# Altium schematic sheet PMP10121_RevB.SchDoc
size 431 x 279 mm; Date: Not shown in title block; ApprovedBy: Not shown in title block; CheckedBy: Not shown in title block; Author: Not shown in title block; CompanyName: Not shown in title block; Engineer: Not shown in title block; Organization: Not shown in title block; Address1: Not shown in title block; Address2: Not shown in title block; Address3: Not shown in title block; Address4: Not shown in title block; DocumentNumber: 1; Revision: Use project parameter SCH_Rev; SheetNumber: 2; SheetTotal: 3; PageSetup: Record=PageOptions¦CenterHorizontal=True¦CenterVertical=True¦PrintScale=1.00¦XCorrection=1.00¦YCorrection=1.00¦PrintKind=0¦BorderSize=5000000¦LeftOffset=0¦BottomOffset=0¦Orientation=2¦PaperLength=1000¦PaperWidth=1000¦Scale=100¦PaperSource=15¦PrintQuality=600¦MediaType=1¦DitherType=10¦PaperKind=Letter¦PrintScaleMode=1
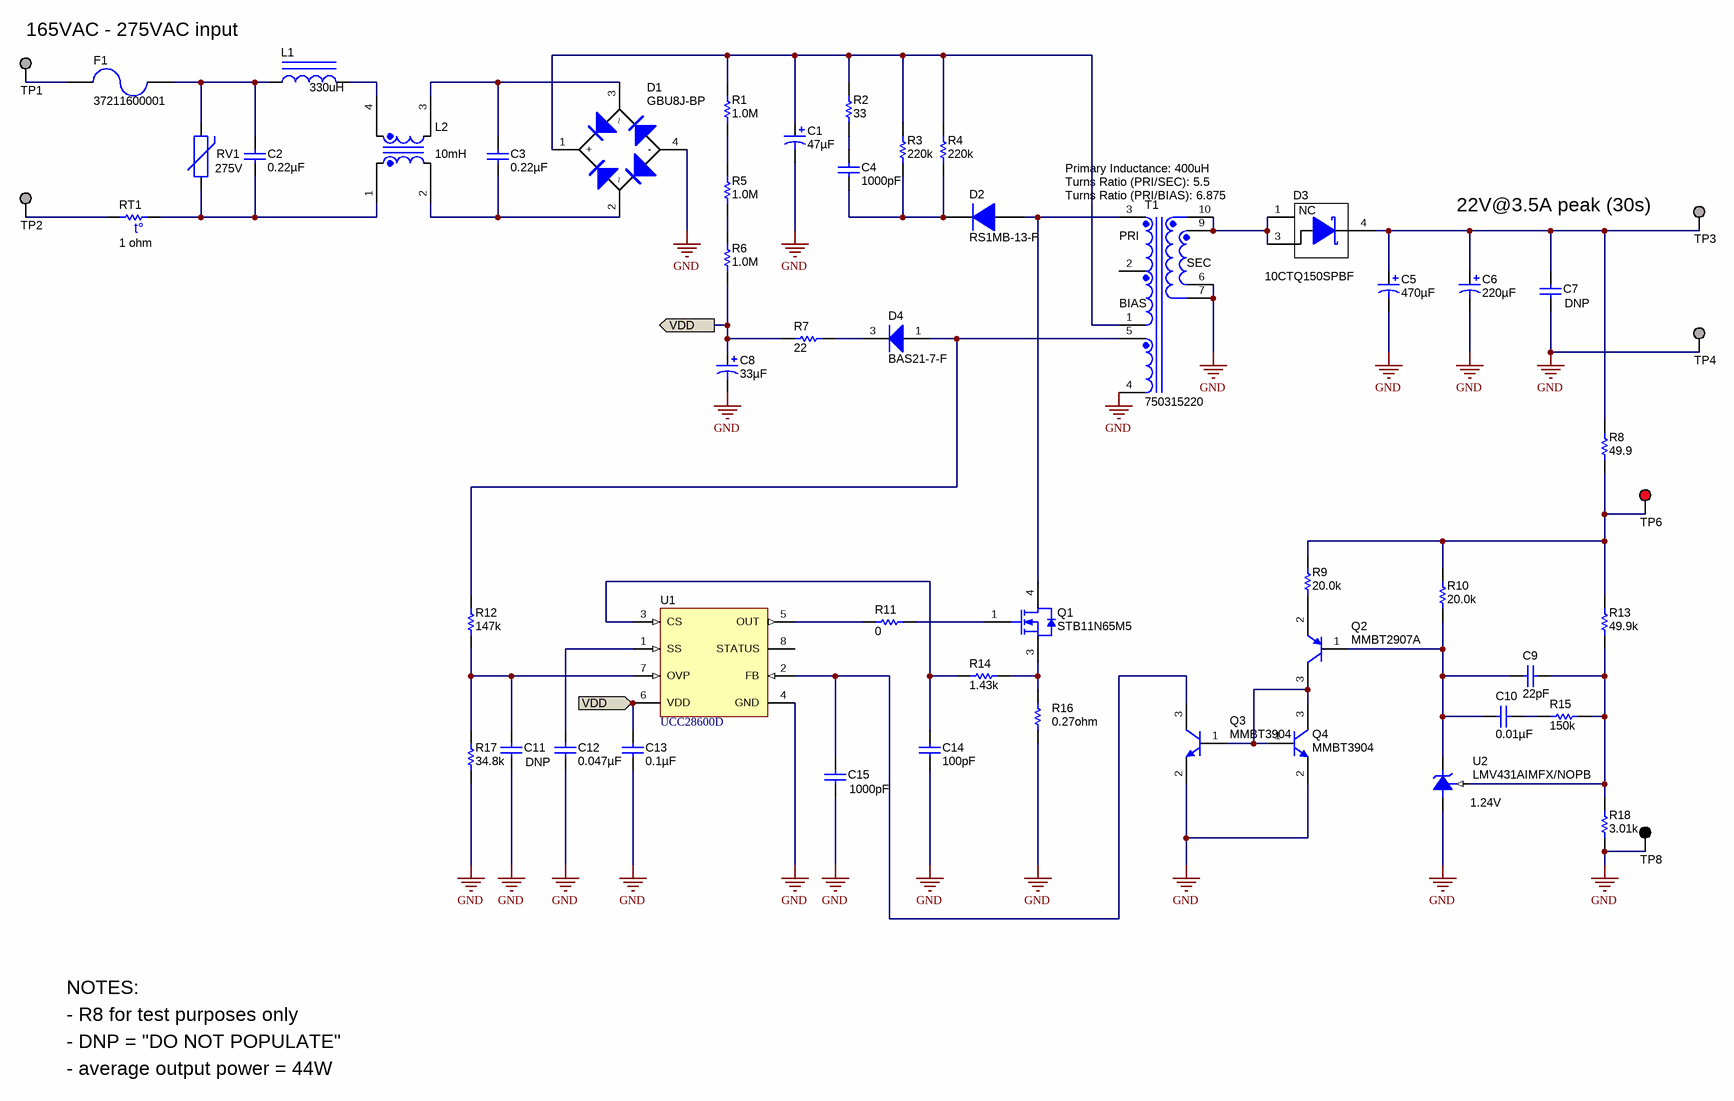
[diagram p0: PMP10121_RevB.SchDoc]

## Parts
C1  ValueDisplayed: 47µF  [CAPPR7.5-18X31.5]  (hidden comment: EEUED2W470)
C2  ValueDisplayed: 0.22µF  [B32922_12.5mm]  (hidden comment: B32922C3224K)
C3  ValueDisplayed: 0.22µF  [B32922_12.5mm]  (hidden comment: B32922C3224K)
C4  ValueDisplayed: 1000pF  [1206]  (hidden comment: GRM31B5C2J102JW01L)
C5  ValueDisplayed: 470µF  [KZN_1000x2000]  (hidden comment: EKZN350ELL471MJ20S)
C6  ValueDisplayed: 220µF  [KZN_800x1500]  (hidden comment: EKZN350ELL221MH15D)
C7  value DNP  [1210]  (hidden comment: Used in BOM report)
C8  ValueDisplayed: 33µF  [SM_RADIAL_E]  (hidden comment: EEE-FC1V330P)
C9  ValueDisplayed: 22pF  [0603]  (hidden comment: GRM1885C1H220JA01D)
C10  ValueDisplayed: 0.01µF  [0805_HV]  (hidden comment: GRM216R71H103KA01D)
C11  value DNP  [0603]  (hidden comment: C0603C100J5GACTU)
C12  ValueDisplayed: 0.047µF  [0603]  (hidden comment: C1608X7R1H473K)
C13  ValueDisplayed: 0.1µF  [0805_HV]  (hidden comment: GRM21BR71H104KA01L)
C14  ValueDisplayed: 100pF  [0603]  (hidden comment: C0603C101J5GAC)
C15  value 1000pF  [0603]  (hidden comment: C1608C0G1H102J)
D1  GBU8J-BP  [GBU]
D2  RS1MB-13-F  [SMB]
D3  10CTQ150SPBF  [DDPAK]
D4  BAS21-7-F  [SOT-23]
F1  37211600001  [FUSE_372]
L1  value 330uH  [IND_MSS1210]  (hidden comment: MSS1210-334KE)
L2  ValueDisplayed: 10mH  [IND_WE-CMB_M]  (hidden comment: 744823210)
Q1  STB11N65M5  [DDPAK]
Q2  MMBT2907A  [SOT-23]
Q3  MMBT3904  [SOT-23]
Q4  MMBT3904  [SOT-23]
R1  ValueDisplayed: 1.0M  [0805_HV]  (hidden comment: CRCW08051M00JNEA)
R2  ValueDisplayed: 33  [2010]  (hidden comment: CRCW201033R0JNEF)
R3  ValueDisplayed: 220k  [2010]  (hidden comment: CRCW2010220KFKEF)
R4  ValueDisplayed: 220k  [2010]  (hidden comment: CRCW2010220KFKEF)
R5  ValueDisplayed: 1.0M  [0805_HV]  (hidden comment: CRCW08051M00JNEA)
R6  ValueDisplayed: 1.0M  [0805_HV]  (hidden comment: CRCW08051M00JNEA)
R7  ValueDisplayed: 22  [0805_HV]  (hidden comment: CRCW080522R0JNEA)
R8  ValueDisplayed: 49.9  [0603]  (hidden comment: CRCW060349R9FKEA)
R9  ValueDisplayed: 20.0k  [0603]  (hidden comment: CRCW060320K0FKEA)
R10  ValueDisplayed: 20.0k  [0603]  (hidden comment: CRCW060320K0FKEA)
R11  ValueDisplayed: 0  [0805_HV]  (hidden comment: CRCW08050000Z0EA)
R12  ValueDisplayed: 147k  [0603]  (hidden comment: CRCW0603147KFKEA)
R13  ValueDisplayed: 49.9k  [0603]  (hidden comment: CRCW060349K9FKEA)
R14  ValueDisplayed: 1.43k  [0603]  (hidden comment: CRCW06031K43FKEA)
R15  ValueDisplayed: 150k  [0603]  (hidden comment: CRCW0603150KFKEA)
R16  value 0.27ohm  [1210]  (hidden comment: Used in BOM report)
R17  ValueDisplayed: 34.8k  [0603]  (hidden comment: CRCW060334K8FKEA)
R18  ValueDisplayed: 3.01k  [0603]  (hidden comment: CRCW06033K01FKEA)
RT1  value 1 ohm  [S237]  (hidden comment: B57237S109M)
RV1  value 275V  [VAR_S10K275E2]  (hidden comment: S10K275E2)
T1  750315220  [WURTH_750315220]
TP1  Suggest using a net name here  [Keystone1503-2]  (value not drawn)
TP2  Suggest using a net name here  [Keystone1503-2]  (value not drawn)
TP3  Suggest using a net name here  [Keystone1503-2]  (value not drawn)
TP4  Suggest using a net name here  [Keystone1503-2]  (value not drawn)
TP6  5000  [Keystone5000]  (value not drawn)
TP8  5001  [Keystone5001]  (value not drawn)
U1  UCC28600D  [D0008A_N]
U2  LMV431AIMFX/NOPB  [MF03A_N]

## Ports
VDD (in), VDD (out)

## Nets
GND: C1.2(-) C5.2(-) C6.2(-) C7.2 C8.2(-) C11.2 C12.2 C13.2 C14.2 C15.2 D1.4(-) Q3.2(E) Q4.2(E) R16.1 R17.1 R18.1 T1.4 T1.6 T1.7 TP4.1 TP8.1 U1.4(GND) U2.3(A)
VDD: C8.1(+) C13.1 R6.1 R7.1 U1.6(VDD) ; port VDD
NetC1_1: C1.1(+) D1.1(+) R1.2 R2.2 R3.2 R4.2 T1.1
NetC2_1: C2.1 F1.1 L1.1 RV1.2
NetC2_2: C2.2 L2.1 RT1.2 RV1.1
NetC3_1: C3.1 D1.3 L2.3
NetC3_2: C3.2 D1.2 L2.2
NetC4_1: C4.1 R2.1
NetC4_2: C4.2 D2.1(K) R3.1 R4.1
NetC5_1: C5.1(+) C6.1(+) C7.1 D3.4(K) R8.2 TP3.1
NetC9_1: C9.1 R13.1 R15.1 R18.2 U2.1(REF)
NetC9_2: C9.2 C10.1 Q2.1(B) R10.1 U2.2(K)
NetC10_2: C10.2 R15.2
NetC11_1: C11.1 R12.1 R17.2 U1.7(OVP)
NetC12_1: C12.1 U1.1(SS)
NetC14_1: C14.1 R14.1 U1.3(CS)
NetC15_1: C15.1 Q3.3(C) U1.2(FB)
NetD2_2: D2.2(A) Q1.4(D) T1.3
NetD3_1: D3.1(NC) D3.3(A) T1.9 T1.10
NetD4_1: D4.1(A) R12.2 T1.5
NetD4_3: D4.3(K) R7.2
NetF1_2: F1.2 TP1.1
NetL1_2: L1.2 L2.4
NetQ1_1: Q1.1(G) R11.2
NetQ1_3: Q1.3(S) R14.2 R16.2
NetQ2_2: Q2.2(E) R9.1
NetQ2_3: Q2.3(C) Q3.1(B) Q4.1(B) Q4.3(C)
NetR1_1: R1.1 R5.2
NetR5_1: R5.1 R6.2
NetR8_1: R8.1 R9.2 R10.2 R13.2 TP6.1
NetR11_1: R11.1 U1.5(OUT)
NetRT1_1: RT1.1 TP2.1

Not connected (* = marked no-connect by the designer): T1 2; U1 8(STATUS)

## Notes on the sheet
- 165VAC - 275VAC input
- (near T1) Primary Inductance: 400uH
- (near T1) Turns Ratio (PRI/SEC): 5.5
- (near T1) Turns Ratio (PRI/BIAS): 6.875
- (near T1) PRI
- 22V@3.5A peak (30s)
- (near T1) BIAS
- (near T1) SEC
- (near U2) 1.24V
- NOTES:
- - R8 for test purposes only
- - DNP = "DO NOT POPULATE"
- - average output power = 44W

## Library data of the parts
C1 = EEUED2W470: CAP, AL, 47 µF, 450 V, +/- 20%, 0.609529 ohm, TH; Manufacturer: Panasonic; Polarized: Y; CompType: Capacitor; Value: 47uF; U/M: EA; Cap_F: 0.000047; Tolerance_%: 20; VDC_V: 450; Value2: 450V; IRMS_A: 1; TaMin_C: -25; TaMax_C: 105; AC_Derating: 0.3
C2 C3 = B32922C3224K: CAP, Film, 0.22 µF, 630 V, +/- 10%, TH; Manufacturer: EPCOS Inc; Polarized: N; CompType: Capacitor; Value: 0.22uF; U/M: EA; Cap_F: 0.00000022; Tolerance_%: 10; Value1: Unknown; VDC_V: 630; Value2: 630V; TaMax_C: 110
C4 = GRM31B5C2J102JW01L: CAP, CERM, 1000 pF, 630 V, +/- 5%, C0G/NP0, 1206; Manufacturer: MuRata; Polarized: N; CompType: Capacitor; Value: 1000pF; U/M: EA; Cap_F: 0.000000001; Tolerance_%: 5; Value1: Unknown; VDC_V: 630; Value2: 630V; TaMin_C: -55; TaMax_C: 125
C5 = EKZN350ELL471MJ20S: CAP, AL, 470 µF, 35 V, +/- 20%, 0.028 ohm, TH; Manufacturer: Chemi-Con; Polarized: Y; CompType: Capacitor; Value: 470uF; U/M: EA; Cap_F: 0.00047; Tolerance_%: 20; VDC_V: 35; Value2: 35V; ESR_ohm: 0.028; IRMS_A: 2.5; TaMin_C: -40; TaMax_C: 105; Cap_Case: 10x20mm
C6 = EKZN350ELL221MH15D: CAP, AL, 220 µF, 35 V, +/- 20%, 0.059 ohm, TH; Manufacturer: Chemi-Con; Polarized: Y; CompType: Capacitor; Value: 220uF; U/M: EA; Cap_F: 0.00022; Tolerance_%: 20; VDC_V: 35; Value2: 35V; ESR_ohm: 0.059; IRMS_A: 1.6; TaMin_C: -40; TaMax_C: 105; Cap_Case: 8x15mm
C7 = Capacitor: CAP, CERM, xxxF, xxV, [TempCo], xx%, [PackageReference]; Polarized: N; U/M: EA
C8 = EEE-FC1V330P: CAP, AL, 33 µF, 35 V, +/- 20%, 0.4 ohm, SMD; Manufacturer: Panasonic; Polarized: Y; CompType: Capacitor; Value: 33uF; U/M: EA; Cap_F: 0.000033; Tolerance_%: 20; Value1: 0.4 ohm; VDC_V: 35; Value2: 35V; ESR_ohm: 0.4; IRMS_A: 0.15; TaMin_C: -40; TaMax_C: 105; Cap_Case: E
C9 = GRM1885C1H220JA01D: CAP, CERM, 22 pF, 50 V, +/- 5%, C0G/NP0, 0603; Manufacturer: MuRata; Polarized: N; CompType: Capacitor; Value: 22pF; U/M: EA; Cap_F: 0.000000000022; Tolerance_%: 5; Value1: Unknown; VDC_V: 50; Value2: 50V; TaMin_C: -55; TaMax_C: 125
C10 = GRM216R71H103KA01D: CAP, CERM, 0.01 µF, 50 V, +/- 10%, X7R, 0805; Manufacturer: MuRata; Polarized: N; CompType: Capacitor; Value: 0.01uF; U/M: EA; Cap_F: 0.00000001; Tolerance_%: 10; Value1: Unknown; VDC_V: 50; Value2: 50V; TaMin_C: -55; TaMax_C: 125; Cap_Case: 0805
C11 = C0603C100J5GACTU: CAP, CERM, 10 pF, 50 V, +/- 5%, C0G/NP0, 0603; Manufacturer: Kemet; Polarized: N; CompType: Capacitor; U/M: EA; Cap_F: 0.00000000001; Tolerance_%: 5; Value1: Unknown; VDC_V: 50; Value2: 50V; TaMin_C: -55; TaMax_C: 125
C12 = C1608X7R1H473K: CAP, CERM, 0.047 µF, 50 V, +/- 10%, X7R, 0603; Manufacturer: TDK; Polarized: N; CompType: Capacitor; Value: 0.047uF; U/M: EA; Cap_F: 0.000000047; Tolerance_%: 10; ESR_ohm: 0.0234; Value1: 0.0234 ohm; VDC_V: 50; Value2: 50V; TaMin_C: -55; TaMax_C: 125
C13 = GRM21BR71H104KA01L: CAP, CERM, 0.1 µF, 50 V, +/- 10%, X7R, 0805; Manufacturer: MuRata; Polarized: N; CompType: Capacitor; Value: 0.1uF; U/M: EA; Cap_F: 0.0000001; Tolerance_%: 10; Value1: Unknown; VDC_V: 50; Value2: 50V; TaMin_C: -55; TaMax_C: 125; Cap_Case: 0805
C14 = C0603C101J5GAC: CAP, CERM, 100 pF, 50 V, +/- 5%, C0G/NP0, 0603; Manufacturer: Kemet; Polarized: N; CompType: Capacitor; Value: 100pF; U/M: EA; Cap_F: 0.0000000001; Tolerance_%: 5; Value1: Unknown; VDC_V: 50; Value2: 50V; TaMin_C: -55; TaMax_C: 125
C15 = C1608C0G1H102J: CAP, CERM, 1000 pF, 50 V, +/- 5%, C0G/NP0, 0603; Manufacturer: TDK; Polarized: N; CompType: Capacitor; U/M: EA; Cap_F: 0.000000001; Tolerance_%: 5; ESR_ohm: 0.0563; Value1: 0.0563 ohm; VDC_V: 50; Value2: 50V; TaMin_C: -55; TaMax_C: 125
D1 = GBU8J-BP: Diode, Switching-Bridge, 420 V, 8 A, TH; Manufacturer: Micro Commercial Components; U/M: EA; Vf_V: 1; Value: 420V; Value1: 8A; Value2: 1V; Io_A: 8; Vr_V: 420; TJmax_C: 175
D2 = RS1MB-13-F: Diode, P-N, 1000 V, 1 A, SMB; Manufacturer: Diodes Inc.; U/M: EA; Vf_V: 1.3; Value: 1000V; Value1: 1A; Value2: 1.3V; Io_A: 1; Vr_V: 1000; TJmax_C: 150; RJC_CperW: 20
D3 = Diode_Schottky_A3C4: Diode, Schottky, xxV, xxA, [PackageReference]; Manufacturer: Used in BOM report; U/M: EA; Diode Configuration: 1 Pair Common Cathode; Vr_V: 150V; Current - Average Rectified (Io) (per Diode): 5A; Current - Reverse Leakage @ Vr: 50µA @ 150V
D4 = BAS21-7-F: Diode, Switching, 200 V, 0.2 A, SOT-23; Manufacturer: Diodes Inc.; U/M: EA; Vf_V: 1.25; Value: 200V; Value1: 0.2A; Value2: 1.25V; Io_A: 0.2; Vr_V: 200; TJmax_C: 150; RJC_CperW: 500
F1 = 37211600001: Fuse, 1.6 A, 250 V, TH; Manufacturer: Littelfuse; U/M: EA; OpeningTime_200%_max: 2; VDC_V: 250; Irating_A: 1.6; Vdrop: 0.095; Soldering_Wave_MaxTemp_C: 260; Soldering_Wave_MaxTime_s: 5
L1 = MSS1210-334KE: Inductor, Shielded, Ferrite, 330 µH, 1.7 A, 0.317 ohm, SMD; Manufacturer: Coilcraft; Ind_H: 330.0E-6; ValueDisplayed: 330µH; Imax_A: 1.7; Irms: 1.7A @ 40C rise; Isat: 2.2A @ 30% inductance drop; DCR_ohm: 0.317; Value2: 1.7A
L2 = 744823210: Coupled inductor, 10 mH, 2 A, 0.125 ohm, +/- 30%, TH; Manufacturer: Wurth Elektronik eiSos; SymbolCreator: a0412235; Ind_H: 10.0E-3; DCR_ohm: 0.125; Isat: 2; Tolerance_%: 30; Value: 10mH
Q1 = STB11N65M5: MOSFET, N-CH, 710 V, 9 A, DDPAK; Manufacturer: STMicroelectronics; Alternate Manufacturer: None; U/M: EA; ChType: N; Value: 710V; VdsMax_V: 710; Value1: ? ohm; Value2: 17 nC; QgTyp_nC: 17; Vgs_V: 25; IdsMax_A: 9
Q2 = MMBT2907A, Fairchild Semiconductor: Transistor, PNP, 60 V, 0.8 A, SOT-23; CompType: BJT; PNP: 1; NPN: 0; Vceo_V: 60; Vcesat1_V: 1.6; Value: 60 V; IcRated_A: 0.8; Value1: 0.8 A; HfeMax: 300; TaMin_C: -55; TaMax_C: 150; U/M: EA
Q3 Q4 = MMBT3904, Fairchild Semiconductor: Transistor, NPN, 40 V, 0.2 A, SOT-23; CompType: BJT; PNP: 0; NPN: 1; Vceo_V: 40; Vcesat1_V: 0.2; Value: 40 V; Value1: 0.2 A; HfeMax: 300; TaMin_C: -55; TaMax_C: 150; U/M: EA
R1 R5 R6 = CRCW08051M00JNEA: RES, 1.0 M, 5%, 0.125 W, 0805; Manufacturer: Vishay-Dale; CompType: Resistor; Value: 1.0Meg; Res_ohm: 1000000; Value_Code: 1M00; Tolerance_%: 5; Power_W: 0.125; Value2: 0.125W; VDC_V: 150; TempCo: 200 ppm/C; EIA_Code: E24; U/M: EA
R2 = CRCW201033R0JNEF: RES, 33, 5%, 0.75 W, 2010; Manufacturer: Vishay-Dale; CompType: Resistor; Value: 33; Value_Code: 33R0; Tolerance_%: 5; Power_W: 0.75; Value2: 0.75W; VDC_V: 400; TempCo: 200 ppm/C; EIA_Code: E24; U/M: EA
R3 R4 = CRCW2010220KFKEF: RES, 220 k, 1%, 0.75 W, 2010; Manufacturer: Vishay-Dale; CompType: Resistor; Value: 220k; Res_ohm: 220000; Tolerance_%: 1; Power_W: 0.75; Value2: 0.75W; VDC_V: 400; TempCo: 100 ppm/C; U/M: EA
R7 = CRCW080522R0JNEA: RES, 22, 5%, 0.125 W, 0805; Manufacturer: Vishay-Dale; CompType: Resistor; Value: 22; Value_Code: 22R0; Tolerance_%: 5; Power_W: 0.125; Value2: 0.125W; VDC_V: 150; TempCo: 200 ppm/C; EIA_Code: E24; U/M: EA
R8 = CRCW060349R9FKEA: RES, 49.9, 1%, 0.1 W, 0603; Manufacturer: Vishay-Dale; CompType: Resistor; Value: 49.9; Value_Code: 49R9; Tolerance_%: 1; Power_W: 0.1; Value2: 0.1W; VDC_V: 75; TempCo: 100 ppm/C; EIA_Code: E96; U/M: EA
R9 R10 = CRCW060320K0FKEA: RES, 20.0 k, 1%, 0.1 W, 0603; Manufacturer: Vishay-Dale; CompType: Resistor; Value: 20.0k; Res_ohm: 20000; Value_Code: 20k0; Tolerance_%: 1; Power_W: 0.1; Value2: 0.1W; VDC_V: 75; TempCo: 100 ppm/C; EIA_Code: E96; U/M: EA
R11 = CRCW08050000Z0EA: RES, 0, 5%, 0.125 W, 0805; Manufacturer: Vishay-Dale; CompType: Resistor; Value: 0; Value_Code: 0000; Tolerance_%: 5; Power_W: 0.125; Value2: 0.125W; VDC_V: 150; TempCo: 200 ppm/C; EIA_Code: E24; U/M: EA
R12 = CRCW0603147KFKEA: RES, 147 k, 1%, 0.1 W, 0603; Manufacturer: Vishay-Dale; CompType: Resistor; Value: 147k; Res_ohm: 147000; Tolerance_%: 1; Power_W: 0.1; Value2: 0.1W; VDC_V: 75; TempCo: 100 ppm/C; EIA_Code: E96; U/M: EA
R13 = CRCW060349K9FKEA: RES, 49.9 k, 1%, 0.1 W, 0603; Manufacturer: Vishay-Dale; CompType: Resistor; Value: 49.9k; Res_ohm: 49900; Value_Code: 49k9; Tolerance_%: 1; Power_W: 0.1; Value2: 0.1W; VDC_V: 75; TempCo: 100 ppm/C; EIA_Code: E96; U/M: EA
R14 = CRCW06031K43FKEA: RES, 1.43 k, 1%, 0.1 W, 0603; Manufacturer: Vishay-Dale; CompType: Resistor; Value: 1.43k; Res_ohm: 1430; Value_Code: 1k43; Tolerance_%: 1; Power_W: 0.1; Value2: 0.1W; VDC_V: 75; TempCo: 100 ppm/C; EIA_Code: E96; U/M: EA
R15 = CRCW0603150KFKEA: RES, 150 k, 1%, 0.1 W, 0603; Manufacturer: Vishay-Dale; CompType: Resistor; Value: 150k; Res_ohm: 150000; Tolerance_%: 1; Power_W: 0.1; Value2: 0.1W; VDC_V: 75; TempCo: 100 ppm/C; EIA_Code: E96; U/M: EA
R16 = Resistor: RES, xxx ohm, x%, xW, [PackageReference]; U/M: EA
R17 = CRCW060334K8FKEA: RES, 34.8 k, 1%, 0.1 W, 0603; Manufacturer: Vishay-Dale; CompType: Resistor; Value: 34.8k; Res_ohm: 34800; Value_Code: 34k8; Tolerance_%: 1; Power_W: 0.1; Value2: 0.1W; VDC_V: 75; TempCo: 100 ppm/C; EIA_Code: E96; U/M: EA
R18 = CRCW06033K01FKEA: RES, 3.01 k, 1%, 0.1 W, 0603; Manufacturer: Vishay-Dale; CompType: Resistor; Value: 3.01k; Res_ohm: 3010; Value_Code: 3k01; Tolerance_%: 1; Power_W: 0.1; Value2: 0.1W; VDC_V: 75; TempCo: 100 ppm/C; EIA_Code: E96; U/M: EA
RT1 = B57237S109M: Thermistor NTC, 1 ohm, 20%, 15x7mm; Manufacturer: EPCOS Inc; Tolerance_%: 20; Power_W: 3.1; TaMin_C: -55; TaMax_C: 170; U/M: EA
RV1 = S10K275E2: Varistor 275V RMS 10MM Radial, TH; Manufacturer: EPCOS Inc; SymbolCreator: a0412235
T1 = 750315220: Transformer, 400 uH, TH; Manufacturer: Wurth Elektronik eiSos; SymbolCreator: Altium; DCR_Ohm: 0.223; Value: 400 uH; U/M: EA
TP1-TP4 = 1503-2: Terminal, Turret, TH, Double; Manufacturer: Keystone; CompType: Turret Terminal; U/M: EA
TP6 = 5000: Test Point, Miniature, Red, TH; Manufacturer: Keystone; CompType: Test Point Loop; U/M: EA
TP8 = 5001: Test Point, Miniature, Black, TH; Manufacturer: Keystone; CompType: Test Point Loop; U/M: EA
U1 = UCC28600D: Quasi-Resonant Flyback Green-Mode Controller with Current Control, 99 % Duty Cycle, -40 to +105 degC, 8-pin SOIC (D), Green (RoHS & no Sb/Br); Manufacturer: Texas Instruments; Alternate Manufacturer: None; Alternate PartNumber: Equivalent; Duty Cycle(Max)(%): 99; Frequency(Max)(kHz): 130; Rating: Catalog; Regulated Outputs(#): 1; SubFamily: PWM Controller; UVLO Thresholds On/Off(V): 10.3/9.3
U2 = LMV431AIMFX/NOPB: Low-Voltage (1.24V) Adjustable Precision Shunt Regulators, 3-pin SOT-23, Pb-Free; Manufacturer: Texas Instruments; PackageTopMarking: RLA*XTT; PowerWise: N; CompType: MiscPower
